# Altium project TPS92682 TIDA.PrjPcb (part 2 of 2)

## Sheet TIDA_Sheet2.SchDoc
size 431 x 279 mm; Date: Not shown in title block; ApprovedBy: Not shown in title block; CheckedBy: Not shown in title block; Author: Not shown in title block; CompanyName: Not shown in title block; Engineer: Not shown in title block; Organization: Not shown in title block; Address1: Not shown in title block; Address2: Not shown in title block; Address3: Not shown in title block; Address4: Not shown in title block; DocumentNumber: 1; Revision: Use project parameter SCH_Rev; SheetNumber: 2; SheetTotal: 3; PageSetup: Record=PageOptions¦CenterHorizontal=True¦CenterVertical=True¦PrintScale=1.00¦XCorrection=1.00¦YCorrection=1.00¦PrintKind=0¦BorderSize=5000000¦LeftOffset=0¦BottomOffset=0¦Orientation=2¦PaperLength=1000¦PaperWidth=1000¦Scale=100¦PaperSource=15¦PrintQuality=600¦MediaType=1¦DitherType=10¦PaperKind=Letter¦PrintScaleMode=1
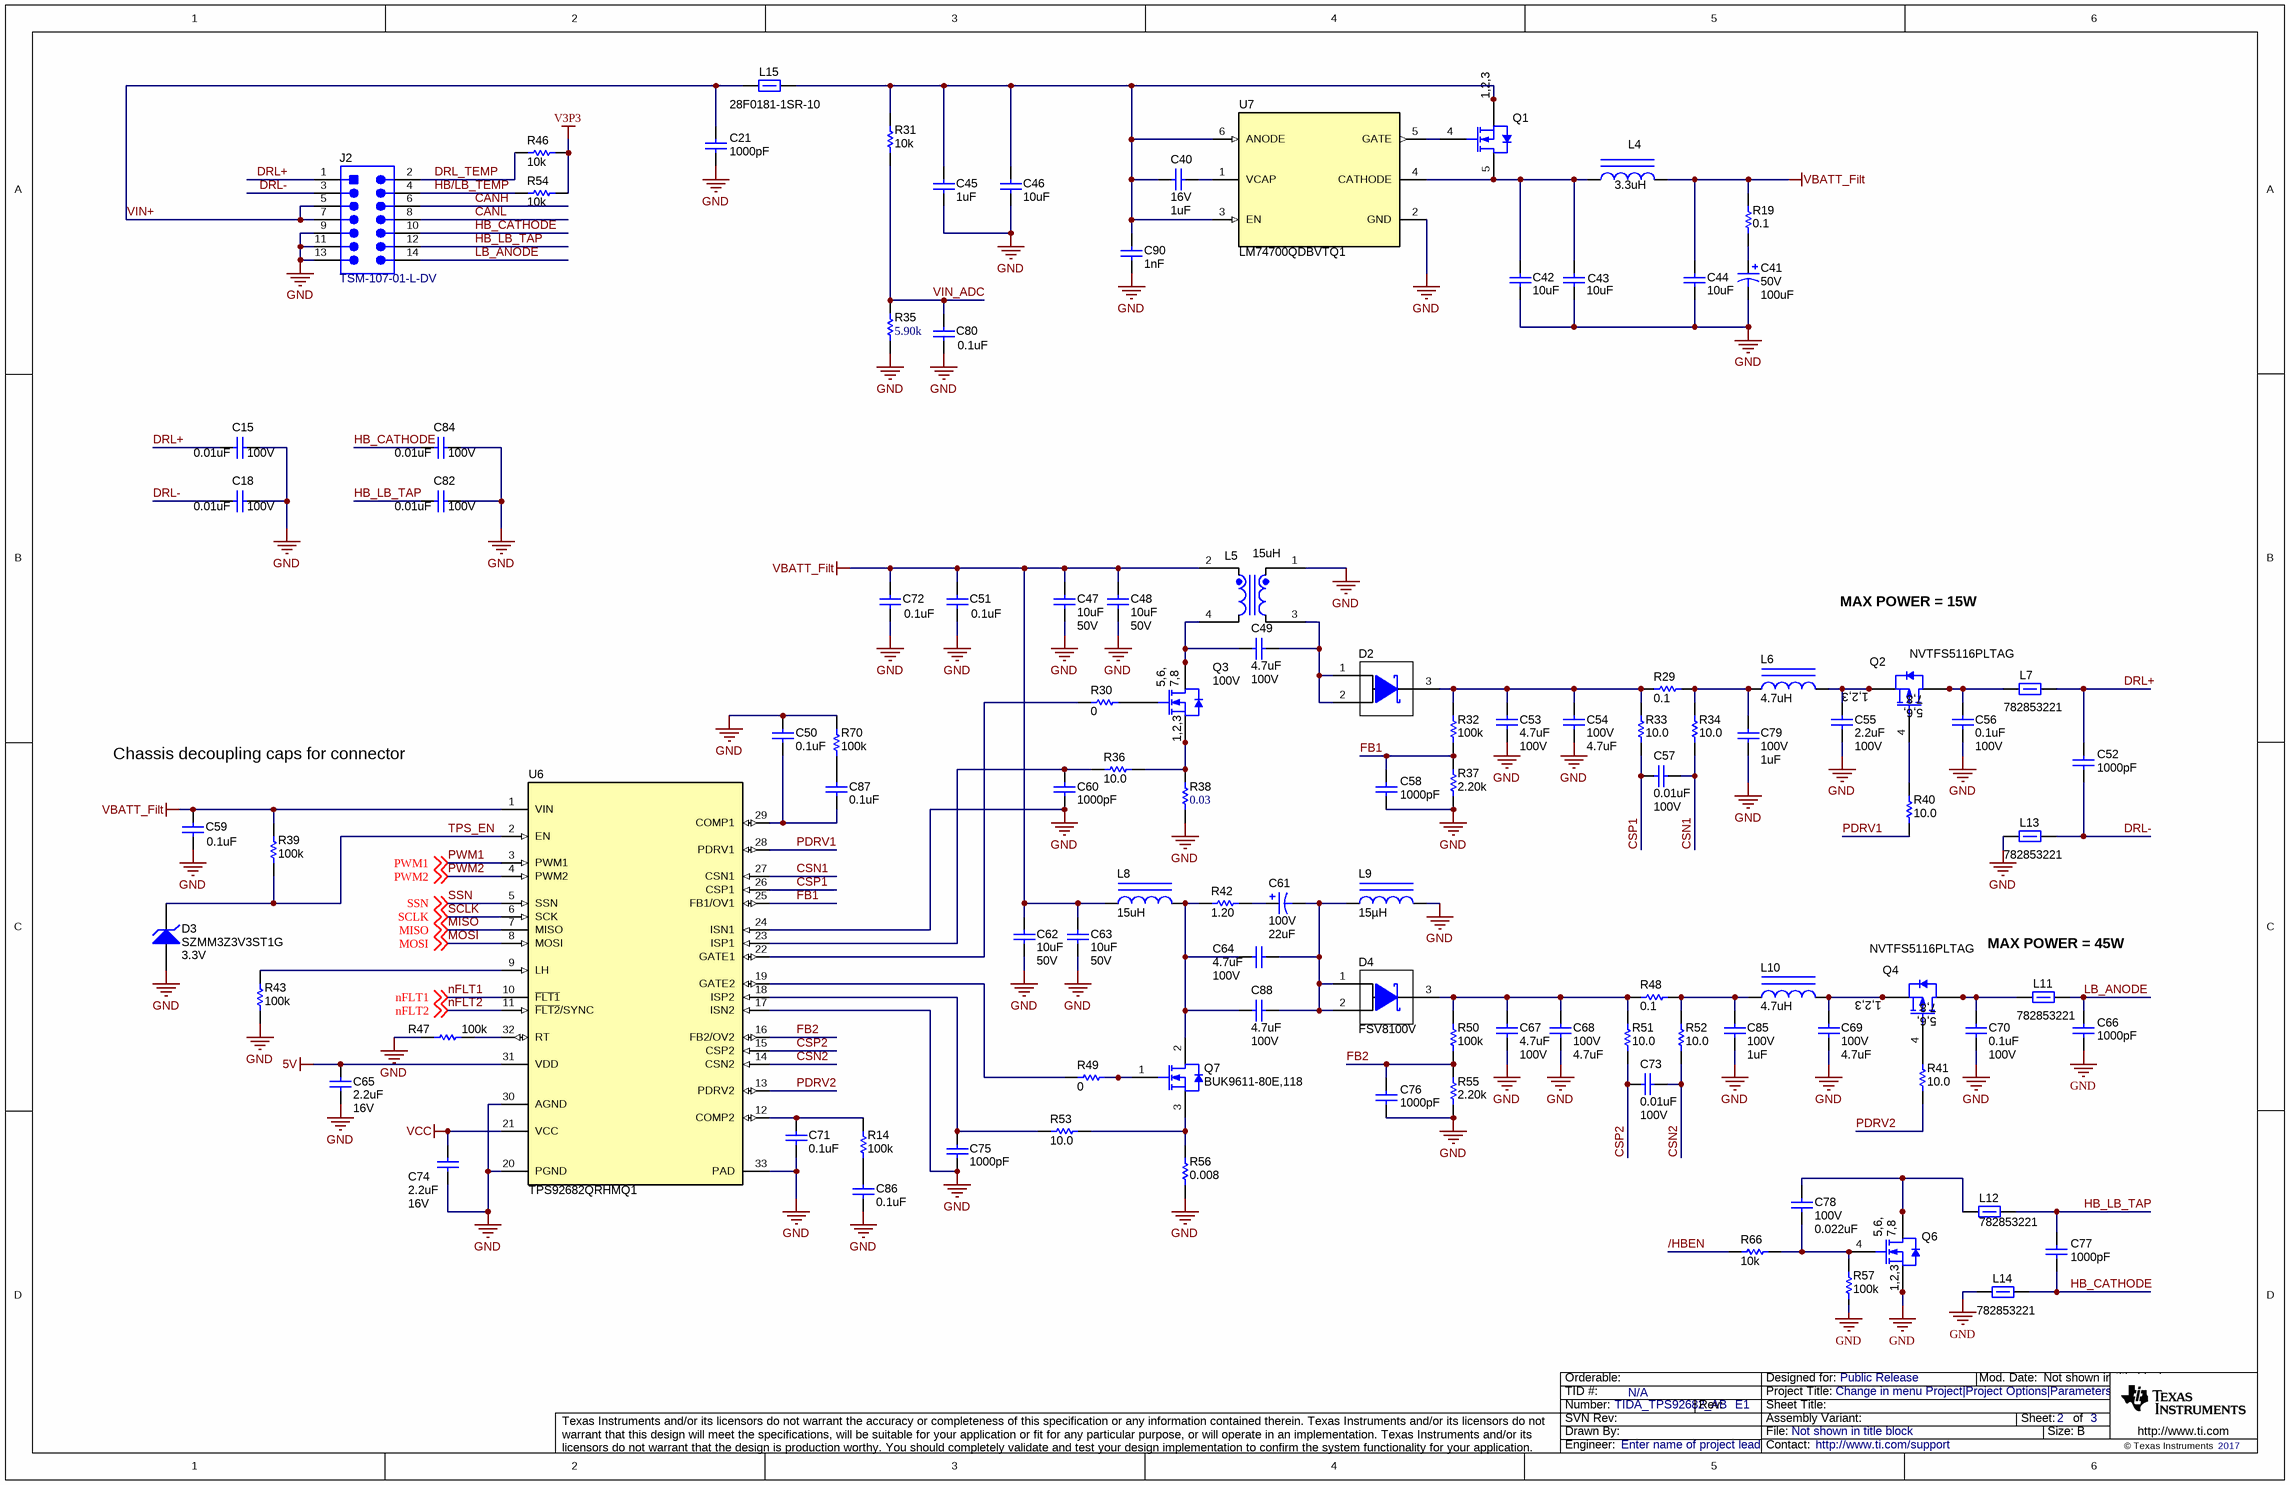
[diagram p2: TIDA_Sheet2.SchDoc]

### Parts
C15  VDC_V: 100V  ValueDisplayed: 0.01uF  [0603]  (hidden comment: GRM188R72A103KA01D)
C18  VDC_V: 100V  ValueDisplayed: 0.01uF  [0603]  (hidden comment: GRM188R72A103KA01D)
C21  ValueDisplayed: 1000pF  [0402]  (hidden comment: CGA2B2X7R1H102K050BA)
C40  VDC_V: 16V  ValueDisplayed: 1uF  [0603]  (hidden comment: GCM188R71C105KA64D)
C41  VDC_V: 50V  ValueDisplayed: 100uF  [SM_RADIAL_F]  (hidden comment: EEE-FK1H101P)
C42  ValueDisplayed: 10uF  [1210_280]  (hidden comment: CGA6P3X7S1H106K250AB)
C43  ValueDisplayed: 10uF  [1210_280]  (hidden comment: CGA6P3X7S1H106K250AB)
C44  ValueDisplayed: 10uF  [1210_280]  (hidden comment: CGA6P3X7S1H106K250AB)
C45  ValueDisplayed: 1uF  [1206_180]  (hidden comment: CGA5L3X7R1H105K160AB)
C46  ValueDisplayed: 10uF  [1210_280]  (hidden comment: CGA6P3X7S1H106K250AB)
C47  ValueDisplayed: 10uF  VDC_V: 50V  [1210_280]  (hidden comment: CGA6P3X7S1H106K250AB)
C48  ValueDisplayed: 10uF  VDC_V: 50V  [1210_280]  (hidden comment: CGA6P3X7S1H106K250AB)
C49  ValueDisplayed: 4.7uF  VDC_V: 100V  [1210_220]  (hidden comment: CGA6M3X7S2A475K200AB)
C50  ValueDisplayed: 0.1uF  [0402]  (hidden comment: CGA2B3X7R1H104M050BB)
C51  ValueDisplayed: 0.1uF  [0603]  (hidden comment: CGA3E3X7S2A104K080AB)
C52  ValueDisplayed: 1000pF  [0402]  (hidden comment: CGA2B2X7R1H102K050BA)
C53  ValueDisplayed: 4.7uF  VDC_V: 100V  [1210_220]  (hidden comment: CGA6M3X7S2A475K200AB)
C54  VDC_V: 100V  ValueDisplayed: 4.7uF  [1210_220]  (hidden comment: CGA6M3X7S2A475K200AB)
C55  ValueDisplayed: 2.2uF  VDC_V: 100V  [1206_180]  (hidden comment: CGA5L3X7S2A225K160AB)
C56  ValueDisplayed: 0.1uF  VDC_V: 100V  [1206_180]  (hidden comment: CGA5L2X7R2A104K160AA)
C57  ValueDisplayed: 0.01uF  Value2: 100V  [0603_HV]  (hidden comment: Capacitor)
C58  ValueDisplayed: 1000pF  [0402]  (hidden comment: CGA2B2X7R1H102K050BA)
C59  ValueDisplayed: 0.1uF  [0603]  (hidden comment: CGA3E3X7S2A104K080AB)
C60  ValueDisplayed: 1000pF  [0402]  (hidden comment: CGA2B2X7R1H102K050BA)
C61  VDC_V: 100V  ValueDisplayed: 22uF  [SM_RADIAL_F]  (hidden comment: EEE-FK2A220P)
C62  ValueDisplayed: 10uF  VDC_V: 50V  [1210_280]  (hidden comment: CGA6P3X7S1H106K250AB)
C63  ValueDisplayed: 10uF  VDC_V: 50V  [1210_280]  (hidden comment: CGA6P3X7S1H106K250AB)
C64  ValueDisplayed: 4.7uF  VDC_V: 100V  [1210_220]  (hidden comment: CGA6M3X7S2A475K200AB)
C65  ValueDisplayed: 2.2uF  Value2: 16V  [0603_HV]  (hidden comment: Capacitor)
C66  ValueDisplayed: 1000pF  [0402]  (hidden comment: CGA2B2X7R1H102K050BA)
C67  ValueDisplayed: 4.7uF  VDC_V: 100V  [1210_220]  (hidden comment: CGA6M3X7S2A475K200AB)
C68  VDC_V: 100V  ValueDisplayed: 4.7uF  [1210_220]  (hidden comment: CGA6M3X7S2A475K200AB)
C69  VDC_V: 100V  ValueDisplayed: 4.7uF  [1210_220]  (hidden comment: CGA6M3X7S2A475K200AB)
C70  ValueDisplayed: 0.1uF  VDC_V: 100V  [1206_180]  (hidden comment: CGA5L2X7R2A104K160AA)
C71  ValueDisplayed: 0.1uF  [0402]  (hidden comment: CGA2B3X7R1H104M050BB)
C72  ValueDisplayed: 0.1uF  [0603]  (hidden comment: CGA3E3X7S2A104K080AB)
C73  ValueDisplayed: 0.01uF  Value2: 100V  [0603_HV]  (hidden comment: Capacitor)
C74  ValueDisplayed: 2.2uF  Value2: 16V  [0603_HV]  (hidden comment: Capacitor)
C75  ValueDisplayed: 1000pF  [0402]  (hidden comment: CGA2B2X7R1H102K050BA)
C76  ValueDisplayed: 1000pF  [0402]  (hidden comment: CGA2B2X7R1H102K050BA)
C77  ValueDisplayed: 1000pF  [0402]  (hidden comment: CGA2B2X7R1H102K050BA)
C78  VDC_V: 100V  ValueDisplayed: 0.022uF  [0603]  (hidden comment: CGA3E2X7R2A223K080AA)
C79  VDC_V: 100V  ValueDisplayed: 1uF  [1206_180]  (hidden comment: CGA5L2X7R2A105K160AA)
C80  ValueDisplayed: 0.1uF  [0603]  (hidden comment: CGA3E3X7S2A104K080AB)
C82  VDC_V: 100V  ValueDisplayed: 0.01uF  [0603]  (hidden comment: GRM188R72A103KA01D)
C84  VDC_V: 100V  ValueDisplayed: 0.01uF  [0603]  (hidden comment: GRM188R72A103KA01D)
C85  VDC_V: 100V  ValueDisplayed: 1uF  [1206_180]  (hidden comment: CGA5L2X7R2A105K160AA)
C86  ValueDisplayed: 0.1uF  [0402]  (hidden comment: CGA2B3X7R1H104M050BB)
C87  ValueDisplayed: 0.1uF  [0402]  (hidden comment: CGA2B3X7R1H104M050BB)
C88  ValueDisplayed: 4.7uF  VDC_V: 100V  [1210_220]  (hidden comment: CGA6M3X7S2A475K200AB)
C90  ValueDisplayed: 1nF  [0603]  (hidden comment: Capacitor)
D2  PDS3100Q-13  [POWERDI5]  (value not drawn)
D3  SZMM3Z3V3ST1G  value 3.3V  [SOD-323]
D4  FSV8100V  [TO-277A]
J2  TSM-107-01-L-DV  [Samtec_TSM-107-01-x-DV]
L4  ValueDisplayed: 3.3uH  [XAL7070]  (hidden comment: XAL7070-332MEB)
L5  value 15uH  [B82477D4]  (hidden comment: B82477D4333M000)
L6  ValueDisplayed: 4.7uH  [IHLP-1616BZ]  (hidden comment: IHLP1616BZER4R7M11)
L7  782853221  [0805_HV]
L8  ValueDisplayed: 15uH  [XAL1510]  (hidden comment: XAL1510-153MEB)
L9  ValueDisplayed: 15µH  [CLF10060NI-D]  (hidden comment: CLF10060NIT-150M-D)
L10  ValueDisplayed: 4.7uH  [IHLP-1616BZ]  (hidden comment: IHLP1616BZER4R7M11)
L11  782853221  [0805_HV]
L12  782853221  [0805_HV]
L13  782853221  [0805_HV]
L14  782853221  [0805_HV]
L15  28F0181-1SR-10  [28F0181]
Q1  NVMFS5C604NLT1G  [TRANS_DFN5]  (value not drawn)
Q2  NVTFS5116PLTAG  [Power_WDFN-8]
Q3  VdsMax_V: 100V  [PowerFLAT5x6_R]  (hidden comment: STL8N10LF3)
Q4  NVTFS5116PLTAG  [Power_WDFN-8]
Q6  MOSFET_N_D56789G4S123  [PowerDI3333-8]  (value not drawn)
Q7  BUK9611-80E,118  [DDPAK]
R14  ValueDisplayed: 100k  [0402]  (hidden comment: CRCW0402100KFKED)
R19  ValueDisplayed: 0.1  [2512]  (hidden comment: CSRN2512FTR100)
R29  ValueDisplayed: 0.1  [1206]  (hidden comment: Resistor)
R30  ValueDisplayed: 0  [0603_HV]  (hidden comment: Resistor)
R31  ValueDisplayed: 10k  [0603]  (hidden comment: Resistor)
R32  ValueDisplayed: 100k  [0603_HV]  (hidden comment: Resistor)
R33  ValueDisplayed: 10.0  [0603_HV]  (hidden comment: Resistor)
R34  ValueDisplayed: 10.0  [0603_HV]  (hidden comment: Resistor)
R35  ValueDisplayed: 5.90k  [0603]  (hidden comment: CRCW06035K90FKEA)
R36  ValueDisplayed: 10.0  [0402]  (hidden comment: CRCW040210R0FKED)
R37  ValueDisplayed: 2.20k  [0603_HV]  (hidden comment: Resistor)
R38  ValueDisplayed: 0.03  [2512]  (hidden comment: CRA2512-FZ-R030ELF)
R39  ValueDisplayed: 100k  [0402]  (hidden comment: CRCW0402100KFKED)
R40  ValueDisplayed: 10.0  [0603_HV]  (hidden comment: Resistor)
R41  ValueDisplayed: 10.0  [0603_HV]  (hidden comment: Resistor)
R42  ValueDisplayed: 1.20  [2512]  (hidden comment: CRCW25121R20FKEG)
R43  ValueDisplayed: 100k  [0402]  (hidden comment: CRCW0402100KFKED)
R46  ValueDisplayed: 10k  [0603]  (hidden comment: Resistor)
R47  ValueDisplayed: 100k  [0603_HV]  (hidden comment: Resistor)
R48  ValueDisplayed: 0.1  [1206]  (hidden comment: Resistor)
R49  ValueDisplayed: 0  [0603_HV]  (hidden comment: Resistor)
R50  ValueDisplayed: 100k  [0603_HV]  (hidden comment: Resistor)
R51  ValueDisplayed: 10.0  [0603_HV]  (hidden comment: Resistor)
R52  ValueDisplayed: 10.0  [0603_HV]  (hidden comment: Resistor)
R53  ValueDisplayed: 10.0  [0603_HV]  (hidden comment: Resistor)
R54  ValueDisplayed: 10k  [0603]  (hidden comment: Resistor)
R55  ValueDisplayed: 2.20k  [0603_HV]  (hidden comment: Resistor)
R56  ValueDisplayed: 0.008  [CRE2512-R5_R9]  (hidden comment: CRE2512-FZ-R008E-2)
R57  ValueDisplayed: 100k  [0603]  (hidden comment: CRCW0603100KFKEA)
R66  ValueDisplayed: 10k  [0603]  (hidden comment: Resistor)
R70  ValueDisplayed: 100k  [0402]  (hidden comment: CRCW0402100KFKED)
U6  TPS92682QRHMQ1  [RHM0032A]
U7  LM74700QDBVTQ1  [DBV0006A_N]

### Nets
5V: C65.1 U6.31(VDD)
GND: C15.2 C18.2 C21.2 C41.2(-) C42.2 C43.2 C44.2 C45.2 C46.2 C47.2 C48.2 C50.1 C51.1 C53.1 C54.2 C55.1 C56.2 C58.2 C59.1 C60.1 C62.2 C63.2 C65.2 C66.2 C67.1 C68.2 C69.2 C70.2 C71.2 C72.1 C74.2 C75.1 C76.2 C79.2 C80.1 C82.2 C84.2 C85.2 C86.2 C90.1 D3.2(A) J2.9 J2.11 J2.13 L5.1 L9.2 L13.2 L14.2 Q6.1(S) Q6.2(S) Q6.3(S) R35.1 R37.1 R38.1 R43.2 R47.1 R55.1 R56.1 R57.1 R70.1 U6.17(ISN2) U6.20(PGND) U6.24(ISN1) U6.30(AGND) U6.33(PAD) U7.2(GND)
V3P3: R46.2 R54.2
VBATT_Filt: C44.1 C47.1 C48.1 C51.2 C59.2 C62.1 C63.1 C72.2 L4.2 L5.2 L8.1 R19.2 R39.1 U6.1(VIN)
VCC: C74.1 U6.21(VCC)
/HBEN: R66.2
CANH: J2.6
CANL: J2.8
CSN1: C57.2 R34.1 U6.27(CSN1)
CSN2: C73.2 R52.1 U6.14(CSN2)
CSP1: C57.1 R33.1 U6.26(CSP1)
CSP2: C73.1 R51.1 U6.15(CSP2)
DRL+: C15.1 C52.1 J2.1 L7.1
DRL-: C18.1 C52.2 J2.3 L13.1
DRL_TEMP: J2.2 R46.1
FB1: C58.1 R32.1 R37.2 U6.25(FB1/OV1)
FB2: C76.1 R50.1 R55.2 U6.16(FB2/OV2)
HB/LB_TEMP: J2.4 R54.1
HB_CATHODE: C77.2 C84.1 J2.10 L14.1
HB_LB_TAP: C77.1 C82.1 J2.12 L12.2
LB_ANODE: C66.1 J2.14 L11.1
MISO: U6.7(MISO) ; off-sheet MISO
MOSI: U6.8(MOSI) ; off-sheet MOSI
nFLT1: U6.10(~{FLT1}) ; off-sheet nFLT1
nFLT2: U6.11(~{FLT2}/SYNC) ; off-sheet nFLT2
PDRV1: R40.2 U6.28(PDRV1)
PDRV2: R41.2 U6.13(PDRV2)
PWM1: U6.3(PWM1) ; off-sheet PWM1
PWM2: U6.4(PWM2) ; off-sheet PWM2
SCLK: U6.6(SCK) ; off-sheet SCLK
SSN: U6.5(SSN) ; off-sheet SSN
TPS_EN: D3.1(K) R39.2 U6.2(EN)
VIN+: C21.1 J2.5 J2.7 L15.1
VIN_ADC: C80.2 R31.1 R35.2
NetC40_1: C40.1 U7.1(VCAP)
NetC40_2: C40.2 C45.1 C46.1 C90.2 L15.2 Q1.1(S) Q1.2(S) Q1.3(S) R31.2 U7.3(EN) U7.6(ANODE)
NetC41_1: C41.1(+) R19.1
NetC42_1: C42.1 C43.1 L4.1 Q1.5(D) Q1.6(D) U7.4(CATHODE)
NetC49_1: C49.1 L5.4 Q3.5(D) Q3.6(D) Q3.7(D) Q3.8(D) Q3.9(D)
NetC49_2: C49.2 D2.1(A) D2.2(A) L5.3
NetC50_2: C50.2 C87.2 U6.29(COMP1)
NetC53_2: C53.2 C54.1 D2.3(K) R29.1 R32.2 R33.2
NetC55_2: C55.2 L6.2 Q2.1(S) Q2.2(S) Q2.3(S)
NetC56_1: C56.1 L7.2 Q2.5(D) Q2.6(D) Q2.7(D) Q2.8(D)
NetC60_2: C60.2 R36.2 U6.23(ISP1)
NetC61_1: C61.1(+) R42.2
NetC61_2: C61.2(-) C64.2 C88.2 D4.1(A) D4.2(A) L9.1
NetC64_1: C64.1 C88.1 L8.2 Q7.2(D) R42.1
NetC67_2: C67.2 C68.1 D4.3(K) R48.1 R50.2 R51.2
NetC69_1: C69.1 L10.2 Q4.1(S) Q4.2(S) Q4.3(S)
NetC70_1: C70.1 L11.2 Q4.5(D) Q4.6(D) Q4.7(D) Q4.8(D)
NetC71_1: C71.1 R14.1 U6.12(COMP2)
NetC75_2: C75.2 R53.2 U6.18(ISP2)
NetC78_1: C78.1 L12.1 Q6.5(D) Q6.6(D) Q6.7(D) Q6.8(D) Q6.9(D)
NetC78_2: C78.2 Q6.4(G) R57.2 R66.1
NetC79_1: C79.1 L6.1 R29.2 R34.2
NetC85_1: C85.1 L10.1 R48.2 R52.2
NetC86_1: C86.1 R14.2
NetC87_1: C87.1 R70.2
NetQ1_4: Q1.4(G) U7.5(GATE)
NetQ2_4: Q2.4(G) R40.1
NetQ3_1: Q3.1(S) Q3.2(S) Q3.3(S) R36.1 R38.2
NetQ3_4: Q3.4(G) R30.1
NetQ4_4: Q4.4(G) R41.1
NetQ7_1: Q7.1(G) R49.1
NetQ7_3: Q7.3(S) R53.1 R56.2
NetR30_2: R30.2 U6.22(GATE1)
NetR43_1: R43.1 U6.9(LH)
NetR47_2: R47.2 U6.32(RT)
NetR49_2: R49.2 U6.19(GATE2)

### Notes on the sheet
- MAX POWER = 15W
- Chassis decoupling caps for connector
- MAX POWER = 45W

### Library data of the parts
C15 C18 C82 C84 = CMP-0007468-5: CAP, CERM, 0.01 uF, 100 V, +/- 10%, X7R, 0603; Manufacturer: MuRata; TaMin_C: -55°C; Polarized: N; SizeAreaWB_mm2: 4.68; Value1: Unknown; U/M: EA; Value: 0.01uF; TaMax_C: 125°C; SizeZ_mm: 1; SizeX_mm: 1.6; SizeY_mm: 0.8; SizeArea_mm2: 1.28; CompType: Capacitor; Cap_F: 10nF; AEC Category: Q200
C21 C52 C58 C66 C76 C77 = CMP-0006314-2: CAP, CERM, 1000 pF, 50 V, +/- 10%, X7R, AEC-Q200 Grade 1, 0402; Manufacturer: TDK; TaMin_C: -55°C; ESR_ohm: 2.25564; Polarized: N; SizeAreaWB_mm2: 3; Value1: 2.25564 ohm; U/M: EA; Value: 1000pF; TaMax_C: 125°C; SizeZ_mm: 0.6; SizeX_mm: 1; SizeY_mm: 0.5; Value2: 50V; CompType: Capacitor; AEC Qualified: Y; Cap_F: 1nF; IRMS_A: 2.80466dA; AEC Category: Q200
C40 = CMP-0007136-5: CAP, CERM, 1 uF, 16 V, +/- 10%, X7R, AEC-Q200 Grade 1, 0603; Manufacturer: MuRata; TaMin_C: -55°C; Polarized: N; SizeAreaWB_mm2: 4.68; Value1: Unknown; U/M: EA; Value: 1uF; TaMax_C: 125°C; SizeZ_mm: 1; SizeX_mm: 1.6; SizeY_mm: 0.8; SizeArea_mm2: 1.28; AEC Qualified: Y; Cap_F: 1µF; AEC Category: Q200
C41 = CMP-0011177-2: CAP, AL, 100 uF, 50 V, +/- 20%, 0.34 ohm, AEC-Q200 Grade 2, SMD; Manufacturer: Panasonic; TaMin_C: -55°C; ESR_ohm: 3.4d; Polarized: Y; SizeAreaWB_mm2: 123.6; U/M: EA; Value: 100uF; TaMax_C: 105°C; SizeZ_mm: 10.2; SizeX_mm: 10; SizeY_mm: 8.3; Cap_Case: F; SizeArea_mm2: 83; CompType: Capacitor; Cap_F: 100µF; IRMS_A: 3.5dA; AEC Grade: 2; AEC Category: Q200
C42-C44 C46 = CMP-0009164-2: CAP, CERM, 10 uF, 50 V, +/- 10%, X7S, AEC-Q200 Grade 1, 1210; Manufacturer: TDK; Polarized: N; CompType: Capacitor; Value: 10uF; U/M: EA; Cap_F: 10µF; ESR_ohm: 2.827m; Value1: 0.002827 ohm; VDC_V: 50V; IRMS_A: 4.37286A; TaMin_C: -55°C; TaMax_C: 125°C; SizeArea_mm2: 8; SizeAreaWB_mm2: 14.7; SizeX_mm: 3.2; SizeY_mm: 2.5; SizeZ_mm: 2.8; AEC Category: Q200; AEC Qualified: Y; AEC Grade: 1
C45 = CMP-0008786-2: CAP, CERM, 1 uF, 50 V, +/- 10%, X7R, AEC-Q200 Grade 1, 1206; Manufacturer: TDK; Polarized: N; CompType: Capacitor; Value: 1uF; U/M: EA; Cap_F: 1µF; ESR_ohm: 9.289m; Value1: 0.009289 ohm; VDC_V: 50V; IRMS_A: 2.38446A; TaMin_C: -55°C; TaMax_C: 125°C; SizeArea_mm2: 5.12; SizeAreaWB_mm2: 10.92; SizeX_mm: 3.2; SizeY_mm: 1.6; SizeZ_mm: 1.8; AEC Category: Q200; AEC Qualified: Y; AEC Grade: 1
C47 C48 C62 C63 = CMP-0009164-2: CAP, CERM, 10 uF, 50 V, +/- 10%, X7S, AEC-Q200 Grade 1, 1210; Manufacturer: TDK; Polarized: N; Value: 10uF; U/M: EA; Cap_F: 10µF; ESR_ohm: 2.827m; Value1: 0.002827 ohm; IRMS_A: 4.37286A; TaMin_C: -55°C; TaMax_C: 125°C; SizeArea_mm2: 8; SizeAreaWB_mm2: 14.7; SizeX_mm: 3.2; SizeY_mm: 2.5; SizeZ_mm: 2.8; AEC Category: Q200; AEC Qualified: Y; AEC Grade: 1
C49 = CMP-0009150-2: CAP, CERM, 4.7 uF, 100 V, +/- 10%, X7S, AEC-Q200 Grade 1, 1210; Manufacturer: TDK; Polarized: N; CompType: Capacitor; Value: 4.7uF; U/M: EA; Cap_F: 4.7µF; ESR_ohm: 4.236m; Value1: 0.004236 ohm; IRMS_A: 3.57337A; TaMin_C: -55°C; TaMax_C: 125°C; SizeArea_mm2: 8; SizeAreaWB_mm2: 14.7; SizeX_mm: 3.2; SizeY_mm: 2.5; SizeZ_mm: 2.2; AEC Category: Q200; AEC Qualified: Y; AEC Grade: 1
C50 C71 C86 C87 = CMP-0006326-2: CAP, CERM, 0.1 uF, 50 V, +/- 20%, X7R, AEC-Q200 Grade 1, 0402; Manufacturer: TDK; Polarized: N; CompType: Capacitor; Value: 0.1uF; U/M: EA; Cap_F: 100nF; Value1: Unknown; VDC_V: 50V; TaMin_C: -55°C; TaMax_C: 125°C; SizeArea_mm2: 0.5; SizeAreaWB_mm2: 3; SizeX_mm: 1; SizeZ_mm: 0.6; AEC Category: Q200; AEC Qualified: Y
C51 C59 C72 C80 = CMP-0007099-4: CAP, CERM, 0.1 uF, 100 V, +/- 10%, X7S, AEC-Q200 Grade 1, 0603; Manufacturer: TDK; TaMin_C: -55°C; ESR_ohm: 0.04959; Polarized: N; SizeAreaWB_mm2: 4.68; Value1: 0.04959 ohm; U/M: EA; Value: 0.1uF; TaMax_C: 125°C; SizeZ_mm: 1; SizeX_mm: 1.6; SizeY_mm: 0.8; Value2: 100V; SizeArea_mm2: 1.28; CompType: Capacitor; AEC Qualified: Y; Cap_F: 100nF; IRMS_A: 7.51618dA; AEC Category: Q200
C53 C64 C67 C88 = CMP-0009150-2: CAP, CERM, 4.7 uF, 100 V, +/- 10%, X7S, AEC-Q200 Grade 1, 1210; Manufacturer: TDK; Polarized: N; Value: 4.7uF; U/M: EA; Cap_F: 4.7µF; ESR_ohm: 4.236m; Value1: 0.004236 ohm; IRMS_A: 3.57337A; TaMin_C: -55°C; TaMax_C: 125°C; SizeArea_mm2: 8; SizeAreaWB_mm2: 14.7; SizeX_mm: 3.2; SizeY_mm: 2.5; SizeZ_mm: 2.2; AEC Category: Q200; AEC Qualified: Y; AEC Grade: 1
C54 C68 C69 = CMP-0009150-2: CAP, CERM, 4.7 uF, 100 V, +/- 10%, X7S, AEC-Q200 Grade 1, 1210; Manufacturer: TDK; TaMin_C: -55°C; ESR_ohm: 4.236m; Polarized: N; SizeAreaWB_mm2: 14.7; Value1: 0.004236 ohm; U/M: EA; Value: 4.7uF; TaMax_C: 125°C; SizeZ_mm: 2.2; SizeX_mm: 3.2; SizeY_mm: 2.5; SizeArea_mm2: 8; AEC Qualified: Y; Cap_F: 4.7µF; IRMS_A: 3.57337A; AEC Grade: 1; AEC Category: Q200
C55 = CMP-0008790-2: CAP, CERM, 2.2 uF, 100 V, +/- 10%, X7S, AEC-Q200 Grade 1, 1206; Manufacturer: TDK; Polarized: N; Value: 2.2uF; U/M: EA; Cap_F: 2.2µF; ESR_ohm: 5.718m; Value1: 0.005718 ohm; IRMS_A: 3.03632A; TaMin_C: -55°C; TaMax_C: 125°C; SizeArea_mm2: 5.12; SizeAreaWB_mm2: 10.92; SizeX_mm: 3.2; SizeY_mm: 1.6; SizeZ_mm: 1.8; AEC Category: Q200; AEC Qualified: Y; AEC Grade: 1
C56 C70 = CMP-0008778-2: CAP, CERM, 0.1 uF, 100 V, +/- 10%, X7R, AEC-Q200 Grade 1, 1206; Manufacturer: TDK; Polarized: N; Value: 0.1uF; U/M: EA; Cap_F: 100nF; ESR_ohm: 0.030343; Value1: 0.030343 ohm; IRMS_A: 1.33802A; TaMin_C: -55°C; TaMax_C: 125°C; SizeArea_mm2: 5.12; SizeAreaWB_mm2: 10.92; SizeX_mm: 3.2; SizeY_mm: 1.6; SizeZ_mm: 1.8; AEC Category: Q200; AEC Qualified: Y; AEC Grade: 1
C57 C73 = CMP-0007082-4: CAP, CERM, 0.01 uF, 100 V, +/- 10%, X7R, AEC-Q200 Grade 1, 0603; PartNumber: CGA3E2X7R2A103K080AA; Manufacturer: TDK; Polarized: N; Value: 0.01uF; U/M: EA; Cap_F: 10nF; ESR_ohm: 2.35428d; Value1: 0.235428 ohm; IRMS_A: 3.96995dA; TaMin_C: -55°C; TaMax_C: 125°C; Cap_Case: 0603; SizeArea_mm2: 1.28; SizeAreaWB_mm2: 4.68; SizeX_mm: 1.6; SizeY_mm: 0.8; SizeZ_mm: 1; AEC Category: Q200; AEC Qualified: Y
C60 C75 = CMP-0006314-2: CAP, CERM, 1000 pF, 50 V, +/- 10%, X7R, AEC-Q200 Grade 1, 0402; Manufacturer: TDK; Polarized: N; CompType: Capacitor; Value: 1000pF; U/M: EA; Cap_F: 1nF; ESR_ohm: 2.25564; Value1: 2.25564 ohm; VDC_V: 50V; IRMS_A: 2.80466dA; TaMin_C: -55°C; TaMax_C: 125°C; SizeArea_mm2: 0.5; SizeAreaWB_mm2: 3; SizeX_mm: 1; SizeZ_mm: 0.6; AEC Category: Q200; AEC Qualified: Y
C61 = CMP-0011202-2: CAP, AL, 22 uF, 100 V, +/- 20%, 1.3 ohm, AEC-Q200 Grade 2, SMD; Manufacturer: Panasonic; TaMin_C: -55°C; ESR_ohm: 1.3; Polarized: Y; SizeAreaWB_mm2: 123.6; Value1: 1.3 ohm; U/M: EA; Value: 22uF; TaMax_C: 105°C; SizeZ_mm: 10.2; SizeX_mm: 10; SizeY_mm: 8.3; Cap_Case: F; SizeArea_mm2: 83; CompType: Capacitor; Cap_F: 22µF; IRMS_A: 1.3dA; AEC Grade: 2; AEC Category: Q200
C65 C74 = CMP-0007499-4: CAP, CERM, 2.2 uF, 16 V, +/- 10%, X7R, 0603; PartNumber: GRM188Z71C225KE43; Manufacturer: MuRata; Polarized: N; Value: 2.2uF; U/M: EA; Cap_F: 2.2µF; Value1: Unknown; TaMin_C: -55°C; TaMax_C: 125°C; Cap_Case: 0603; SizeArea_mm2: 1.28; SizeAreaWB_mm2: 4.68; SizeX_mm: 1.6; SizeY_mm: 0.8; SizeZ_mm: 1; AEC Category: Q200
C78 = CMP-0007086-4: CAP, CERM, 0.022 uF, 100 V, +/- 10%, X7R, AEC-Q200 Grade 1, 0603; Manufacturer: TDK; TaMin_C: -55°C; ESR_ohm: 0.083542; Polarized: N; SizeAreaWB_mm2: 4.68; Value1: 0.083542 ohm; U/M: EA; TaMax_C: 125°C; SizeZ_mm: 1; SizeX_mm: 1.6; SizeY_mm: 0.8; SizeArea_mm2: 1.28; CompType: Capacitor; AEC Qualified: Y; Cap_F: 22nF; IRMS_A: 6.09312dA; AEC Category: Q200
C79 C85 = CMP-0008779-2: CAP, CERM, 1 uF, 100 V, +/- 10%, X7R, AEC-Q200 Grade 1, 1206; Manufacturer: TDK; TaMin_C: -55°C; ESR_ohm: 4.575m; Polarized: N; SizeAreaWB_mm2: 10.92; Value1: 0.004575 ohm; U/M: EA; Value: 1uF; TaMax_C: 125°C; SizeZ_mm: 1.8; SizeX_mm: 3.2; SizeY_mm: 1.6; SizeArea_mm2: 5.12; AEC Qualified: Y; Cap_F: 1µF; IRMS_A: 3.39639A; AEC Grade: 1; AEC Category: Q200
C90 = CMP-0006993-4: CAP, CERM, 1000 pF, 100 V, +/- 5%, C0G/NP0, 0603; PartNumber: C1608C0G2A102J080AA; Manufacturer: TDK; Polarized: N; Value: 1000pF; U/M: EA; ESR_ohm: 0.0589; Value1: 0.0589 ohm; VDC_V: 100V; TaMin_C: -55°C; TaMax_C: 125°C; SizeArea_mm2: 1.28; SizeAreaWB_mm2: 4.68; SizeX_mm: 1.6; SizeY_mm: 0.8; SizeZ_mm: 1; AEC Category: Q200
D2 = CMP-0028754-2: Diode, Schottky, 100 V, 3 A, AEC-Q101, PowerDI5; Manufacturer: Diodes Inc.; Vf_V: 7.6dV; Value: 100V; Value1: 3A; Value2: 0.76V; TJmax_C: 150°C; SizeAreaWB_mm2: 49.56; SizeArea_mm2: 24.96; SizeX_mm: 6.4; SizeY_mm: 3.9; SizeZ_mm: 1.05; AEC Category: Q101; AEC Qualified: Y; Green_Lifecycle: Active; Green_REACh: Passed
D3 = CMP-0085730-1: Diode, Zener, 3.3 V, 300 mW, AEC-Q101, SOD-323; Manufacturer: ON Semiconductor; RJA_CperW: 416; AEC Qualified: Y; SizeArea_mm2: 3.645; SizeX_mm: 2.7; SizeY_mm: 1.35; SizeZ_mm: 1; AEC Category: Q101; SizeAreaWB_mm2: 8.695; Power_W: 300mW; Value1: 0.3W
D4 = CMP-0028826-1: Diode, Schottky, 100 V, 8 A, AEC-Q101, TO-277A; Manufacturer: Fairchild Semiconductor; Io_A: 8A; Green_Lifecycle: Not Set; SizeAreaWB_mm2: 57.375; Vr_V: 100V; Green_REACh: Incomplete; TJmax_C: 150°C; U/M: EA; Value: 100V; SizeZ_mm: 1.2; SizeX_mm: 6.5; SizeY_mm: 4.75; Vf_V: 6.7dV; Value2: 0.67V; SizeArea_mm2: 30.875; AEC Qualified: Y; AEC Category: Q101
J2 = CMP-0075611-2: Header, 2.54mm, 7x2, Gold, SMT; Manufacturer: Samtec; Pitch_mm: 2.54; Gender: Male; Cert_CSA: Y; Current_A: 5.4A; Shrouded: N; Row_Count: 2
L4 = CMP-0061052-1: Inductor, Shielded, Composite, 3.3 uH, 15.1 A, 0.01 ohm, SMD; Manufacturer: Coilcraft; Value: 3.3uH; Ind_H: 3.3µH; Imax_A: 15.1A; Irms: 15.1A @ 40C rise; Isat: 19.4A @ 30% inductance drop; DCR_ohm: 0.01; SizeAreaWB_mm2: 87.4; SizeArea_mm2: 54; SizeX_mm: 7.2; SizeY_mm: 7.5; SizeZ_mm: 7; AEC Category: Q200; Green_Lifecycle: Not Set; Green_REACh: Incomplete
L5 = CMP-0013101-2: Coupled inductor, 15 uH, 6.5 A, 0.0355 ohm, SMD; Manufacturer: TDK; PartNumber: B82477D4153M000; DCR_ohm: 0.0355
L6 L10 = CMP-0063280-1: Inductor, Shielded Drum Core, Powdered Iron, 4.7 uH, 1.7 A, 0.095 ohm, SMD; Manufacturer: Vishay-Dale; Isat: 1.75A @ 20% inductance drop; Irms: 1.7A @ 40C rise; Green_Lifecycle: Active; SizeAreaWB_mm2: 27.577; DCR_ohm: 0.095; Green_REACh: Passed; Value: 4.7uH; Imax_A: 1.7A; SizeZ_mm: 2; SizeX_mm: 4.45; SizeY_mm: 4.06; SizeArea_mm2: 18.067; Ind_H: 4.7µH; AEC Category: Q200
L7 L11-L14 = CMP-0003297-1: Ferrite Bead, 220 ohm @ 100 MHz, 2 A, 0805; Manufacturer: Wurth Elektronik; Ztyp@1GHz_Ohm: 126.015; ZTyp@100MHz_Ohm: 220; SizeAreaWB_mm2: 6.75; DCR_ohm: 0.05; Value1: 0.05 ohm; Value: 220 ohm; Imax_A: 2A; SizeZ_mm: 1.45; SizeX_mm: 2; SizeY_mm: 1.25; SizeArea_mm2: 2.5
L8 = CMP-0061646-2: Inductor, Shielded, Composite, 15 uH, 18 A, 0.00917 ohm, SMD; Manufacturer: Coilcraft; Isat: 23A @ 30% inductance drop; Irms: 18A @ 40C rise; SizeAreaWB_mm2: 320.16; DCR_ohm: 9.17m; Value: 15uH; Imax_A: 18A; SizeZ_mm: 10; SizeX_mm: 16.4; SizeY_mm: 15.4; SizeArea_mm2: 252.56; Ind_H: 15µH; AEC Category: Q200
L9 = CMP-0080422-3: Inductor, Shielded, Ferrite, 15 µH, 3.3 A, 0.036 ohm, AEC-Q200 Grade 0, SMD; Manufacturer: TDK; Isat: 3.3A @ 30% inductance drop; Irms: 4.1A @ 40C rise; SizeAreaWB_mm2: 145.2; DCR_ohm: 0.036; Value: 15uH; Imax_A: 3.3A; SizeZ_mm: 6.3; SizeX_mm: 10.1; SizeY_mm: 10; SizeArea_mm2: 101; AEC Qualified: Y; AEC Grade: 0; AEC Category: Q200
L15 = CMP-0003060-1: Ferrite Bead, 115 ohm @ 100 MHz, 10 A, SMD, 2-Leads, Body 8.74x4.65mm; Manufacturer: Laird-Signal Integrity Products; ZTyp@100MHz_Ohm: 115; DCR_ohm: 1m; Value1: 0.001 ohm; Value: 115 ohm; Imax_A: 10A
Q1 = CMP-0077633-1: MOSFET, N-CH, 60 V, 287 A, AEC-Q101, DFN5 5x6mm; Manufacturer: ON Semiconductor; Alternate Manufacturer: None; ChType: N; QgTyp_nC: 52.0; SizeAreaWB_mm2: 58.2725; SizeArea_mm2: 31.6725; IdsMax_A: 287A; AEC Qualified: Y; VdsMax_V: 60V; Rdson45_ohm: 1.7m; Vgs_V: 20V; AEC Category: Q101; Value: 60V; SizeZ_mm: 1.0; SizeY_mm: 6.15; Value2: 52 nC; U/M: EA; Value1: 0.0017 ohm; SizeX_mm: 5.15
Q2 Q4 = CMP-0750095-1: MOSFET, P-CH, -60 V, -6 A, AEC-Q101, 8-PowerWDFN; Alternate Manufacturer: None; Manufacturer: ON Semiconductor; Vgs_V: -20V; AEC Category: Q101; IdsMax_A: -6A; SizeZ_mm: 0.8; ChType: P; QgTyp_nC: 14; AEC Qualified: Y; SizeArea_mm2: 10.89; VdsMax_V: -60V; SizeAreaWB_mm2: 18.49; Rdson45_ohm: 0.072; Value1: 0.072 ohm; ChMode: Enhancement; Value2: 14 nC; SizeX_mm: 3.3; Value: -60V
Q3 = CMP-0001033-3: MOSFET, N-CH, 100 V, 20 A, AEC-Q101, 8-PowerVDFN; Alternate Manufacturer: None; Manufacturer: STMicroelectronics; SizeZ_mm: 1; ChType: N; Value2: 20.5 nC; SizeX_mm: 6.15; SizeY_mm: 5.2; Vgs_V: 20V; QgTyp_nC: 20.5; AEC Qualified: Y; Value: 100V; SizeArea_mm2: 31.98; AEC Category: Q101; IdsMax_A: 20A; SizeAreaWB_mm2: 58.68; U/M: EA
Q6 = CMP-0000970-2: MOSFET, N-CH, 100 V, 3.8 A, 8-PowerVDFN; PartNumber: DMN10H120SFG-13; Manufacturer: Diodes Inc.; Alternate Manufacturer: None; U/M: EA; ChType: N; Value: 100V; Value2: 10.6 nC; QgTyp_nC: 10.6; Vgs_V: 20V; IdsMax_A: 3.8A; AEC Category: Q101; SizeArea_mm2: 10.89; SizeAreaWB_mm2: 18.49; SizeX_mm: 3.3; SizeZ_mm: 0.8
Q7 = CMP-0082013-2: MOSFET, N-CH, 80 V, 75 A, AEC-Q101, DDPAK; Alternate Manufacturer: None; Manufacturer: Nexperia; QgTyp_nC: 48.8; Value: 80V; ChMode: Enhancement; SizeX_mm: 15.245; Vgs_V: 15V; Value1: ? ohm; Value2: 48.8 nC; SizeZ_mm: 4.445; AEC Category: Q101; ChType: N; SizeY_mm: 10.16; IdsMax_A: 75A; SizeAreaWB_mm2: 209.6992; AEC Qualified: Y; SizeArea_mm2: 154.8892
R14 R43 R70 = CMP-0025950-3: RES, 100 k, 1%, 0.063 W, AEC-Q200 Grade 0, 0402; Manufacturer: Vishay-Dale; Value: 100k; Power_W: 63mW; Value2: 0.063W; VDC_V: 50V; TempCo: 100 ppm/C; SizeArea_mm2: 0.5; SizeX_mm: 1; SizeZ_mm: 0.6; EIA_Code: E96; AEC Category: Q200; AEC Qualified: Y; AEC Grade: 0
R19 = CMP-0015792-2: RES, 0.1, 1%, 2 W, 2512; Manufacturer: Stackpole Electronics Inc; Power_W: 2W; TempCo: 200 ppm/C; Value_Code: R100; U/M: EA; Value: 0.1; EIA_Code: E96; Res_ohm: 1d; SizeX_mm: 6.3; SizeY_mm: 3.2; SizeZ_mm: 0.71; SizeArea_mm2: 20.16; VDC_V: 200V; AEC Category: Q200
R29 R48 = CMP-0017279-2: RES, 0.1, 1%, 0.5 W, 1206; PartNumber: ERJ-8BWFR100V; Manufacturer: Panasonic; Value: 0.1; Res_ohm: 1d; Value_Code: R100; Power_W: 500mW; Value2: 0.5W; VDC_V: 0V; TempCo: 150 ppm/C; SizeArea_mm2: 5.12; SizeX_mm: 3.2; SizeY_mm: 1.6; SizeZ_mm: 1.35; EIA_Code: E96; U/M: EA; AEC Category: Q200
R30 R49 = CMP-0025697-4: RES, 0, 5%, 0.1 W, AEC-Q200 Grade 0, 0603; PartNumber: CRCW06030000Z0EA; Manufacturer: Vishay-Dale; Value: 0; Value_Code: 0000; Power_W: 100mW; Value2: 0.1W; VDC_V: 75V; TempCo: 200 ppm/C; EIA_Code: E24; AEC Category: Q200; AEC Qualified: Y; SizeArea_mm2: 1.28; SizeX_mm: 1.6; SizeY_mm: 0.8; SizeZ_mm: 1
R31 R46 R54 R66 = CMP-0025701-4: RES, 10 k, 5%, 0.1 W, AEC-Q200 Grade 0, 0603; PartNumber: CRCW060310K0JNEA; Manufacturer: Vishay-Dale; Value: 10k; Value_Code: 10k0; Power_W: 100mW; Value2: 0.1W; VDC_V: 75V; TempCo: 200 ppm/C; EIA_Code: E24; AEC Category: Q200; AEC Qualified: Y; AEC Grade: 0; SizeArea_mm2: 1.28; SizeX_mm: 1.6; SizeY_mm: 0.8; SizeZ_mm: 1
R32 R47 R50 = CMP-0021990-4: RES, 100 k, 1%, 0.1 W, AEC-Q200 Grade 0, 0603; PartNumber: CRCW0603100KFKEA; Manufacturer: Vishay-Dale; Value: 100k; Power_W: 100mW; Value2: 0.1W; VDC_V: 75V; TempCo: 100 ppm/C; EIA_Code: E96; AEC Category: Q200; AEC Grade: 0; AEC Qualified: Y; SizeArea_mm2: 1.28; SizeX_mm: 1.6; SizeY_mm: 0.8; SizeZ_mm: 1
R33 R34 R40 R41 R51-R53 = CMP-0022003-4: RES, 10.0, 1%, 0.1 W, AEC-Q200 Grade 0, 0603; PartNumber: CRCW060310R0FKEA; Manufacturer: Vishay-Dale; Value: 10.0; Res_ohm: 10; Value_Code: 10R0; Power_W: 100mW; Value2: 0.1W; VDC_V: 75V; TempCo: 100 ppm/C; SizeArea_mm2: 1.28; SizeX_mm: 1.6; SizeY_mm: 0.8; SizeZ_mm: 1; EIA_Code: E96; AEC Category: Q200; AEC Qualified: Y; AEC Grade: 0
R35 = CMP-0022515-4: RES, 5.90 k, 1%, 0.1 W, AEC-Q200 Grade 0, 0603; Manufacturer: Vishay-Dale; Power_W: 100mW; TempCo: 100 ppm/C; Value_Code: 5k90; Value: 5.90k; EIA_Code: E96; Res_ohm: 5.9k; SizeX_mm: 1.6; SizeY_mm: 0.8; SizeZ_mm: 1; Value2: 0.1W; SizeArea_mm2: 1.28; AEC Qualified: Y; VDC_V: 75V; AEC Category: Q200; AEC Grade: 0
R36 = CMP-0025963-3: RES, 10.0, 1%, 0.063 W, AEC-Q200 Grade 0, 0402; Manufacturer: Vishay-Dale; Value: 10.0; Res_ohm: 10; Value_Code: 10R0; Power_W: 63mW; Value2: 0.063W; VDC_V: 50V; TempCo: 100 ppm/C; SizeArea_mm2: 0.5; SizeX_mm: 1; SizeZ_mm: 0.6; EIA_Code: E96; AEC Category: Q200; AEC Qualified: Y; AEC Grade: 0
R37 R55 = CMP-0022986-5: RES, 2.20 k, 1%, 0.1 W, 0603; PartNumber: RC0603FR-072K2L; Manufacturer: Yageo; Value: 2.20k; Res_ohm: 2.2k; Value_Code: 2k20; Power_W: 100mW; Value2: 0.1W; VDC_V: 75V; TempCo: 100 ppm/C; SizeArea_mm2: 1.28; SizeX_mm: 1.6; SizeY_mm: 0.8; SizeZ_mm: 1; AEC Category: Q200; AEC Qualified: N; SizeAreaWB_mm2: 4.68
R38 = CMP-0015422-2: RES, 0.03, 1%, 3 W, 2512; Manufacturer: Bourns; Power_W: 3W; TempCo: 75 ppm/C; Value_Code: R030; U/M: EA; Value: 0.03; EIA_Code: E96; SizeX_mm: 6.3; SizeY_mm: 3.2; SizeZ_mm: 0.71; SizeArea_mm2: 20.16; VDC_V: 0V; AEC Category: Q200
R39 = CMP-0025950-3: RES, 100 k, 1%, 0.063 W, AEC-Q200 Grade 0, 0402; Manufacturer: Vishay-Dale; CompType: Resistor; Value: 100k; Power_W: 63mW; Value2: 0.063W; VDC_V: 50V; TempCo: 100 ppm/C; SizeArea_mm2: 0.5; SizeX_mm: 1; SizeZ_mm: 0.6; EIA_Code: E96; AEC Category: Q200; AEC Qualified: Y; AEC Grade: 0
R42 = CMP-0015521-3: RES, 1.20, 1%, 1 W, AEC-Q200 Grade 0, 2512; Manufacturer: Vishay-Dale; Power_W: 1W; TempCo: 100 ppm/C; Value_Code: 1R20; Value: 1.20; Res_ohm: 1.2; SizeX_mm: 6.3; SizeY_mm: 3.2; SizeZ_mm: 0.71; SizeArea_mm2: 20.16; AEC Qualified: Y; VDC_V: 500V; AEC Grade: 0; AEC Category: Q200
R56 = CMP-0074665-1: RES, 0.008, 1%, 2 W, AEC-Q200 Grade 0, 2512; Manufacturer: Bourns; Power_W: 2W; TempCo: 50 ppm/C; Value_Code: 8L000; U/M: EA; Value: 0.008; EIA_Code: E96; Res_ohm: 8m; SizeX_mm: 6.45; SizeY_mm: 3.35; SizeZ_mm: 0.9; SizeArea_mm2: 21.6075; AEC Qualified: Y; AEC Grade: 0; AEC Category: Q200
R57 = CMP-0021990-4: RES, 100 k, 1%, 0.1 W, AEC-Q200 Grade 0, 0603; Manufacturer: Vishay-Dale; Power_W: 100mW; TempCo: 100 ppm/C; Value: 100k; EIA_Code: E96; SizeX_mm: 1.6; SizeY_mm: 0.8; SizeZ_mm: 1; Value2: 0.1W; SizeArea_mm2: 1.28; AEC Qualified: Y; VDC_V: 75V; AEC Category: Q200; AEC Grade: 0
U6 = CMP-0084188-2: Dual Channel Constant Voltage and Constant Current Controller with SPI Interface, RHM0032A (VQFNP-32); Alternate Manufacturer: Texas Instruments; SizeAreaWB_mm2: 49; Rating: Automotive; SizeZ_mm: 0.9; SizeX_mm: 5; SizeArea_mm2: 25; CompType: IC; AEC Qualified: Y; AEC Category: Q200
U7 = CMP-0079180-1: Low Iq Always ON Smart Diode Controller, DBV0006A (SOT-23-6); Alternate PartNumber: LM74700QDBVRQ1; Alternate Manufacturer: Texas Instruments; SizeAreaWB_mm2: 14.82; SizeZ_mm: 1.45; SizeX_mm: 2.8; SizeY_mm: 2.9; SizeArea_mm2: 8.12; CompType: IC; AEC Qualified: Y; AEC Category: Q200

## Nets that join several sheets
GND: TIDA_Sheet1 (57 pins), TIDA_Sheet2 (66 pins)
V3P3: TIDA_Sheet1 (53 pins), TIDA_Sheet2 (R46.2 R54.2)
VBATT_Filt: TIDA_Sheet1 (C32.1 C34.1 R22.2 U4.8), TIDA_Sheet2 (14 pins)
/HBEN: TIDA_Sheet1 (R72.2), TIDA_Sheet2 (R66.2)
CANH: TIDA_Sheet1 (C27.1 L2.3 R23.2 U5.2), TIDA_Sheet2 (J2.6)
CANL: TIDA_Sheet1 (C38.1 L2.2 R25.1 U5.1), TIDA_Sheet2 (J2.8)
DRL_TEMP: TIDA_Sheet1 (C22.1 U1.13), TIDA_Sheet2 (J2.2 R46.1)
HB/LB_TEMP: TIDA_Sheet1 (C1.1 U1.12), TIDA_Sheet2 (J2.4 R54.1)
MISO: TIDA_Sheet1 (R26.1 R61.1), TIDA_Sheet2 (U6.7)
MOSI: TIDA_Sheet1 (R62.1), TIDA_Sheet2 (U6.8)
nFLT1: TIDA_Sheet1 (R44.1 U1.76), TIDA_Sheet2 (U6.10)
nFLT2: TIDA_Sheet1 (R45.1 U1.77), TIDA_Sheet2 (U6.11)
PWM1: TIDA_Sheet1 (R59.2), TIDA_Sheet2 (U6.3)
PWM2: TIDA_Sheet1 (R60.2), TIDA_Sheet2 (U6.4)
SCLK: TIDA_Sheet1 (R63.1), TIDA_Sheet2 (U6.6)
SSN: TIDA_Sheet1 (R71.1), TIDA_Sheet2 (U6.5)
TPS_EN: TIDA_Sheet1 (U1.23), TIDA_Sheet2 (D3.1 R39.2 U6.2)
VIN_ADC: TIDA_Sheet1 (U1.15), TIDA_Sheet2 (C80.2 R31.1 R35.2)

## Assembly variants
001: not fitted FID1 FID2 FID3 R57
